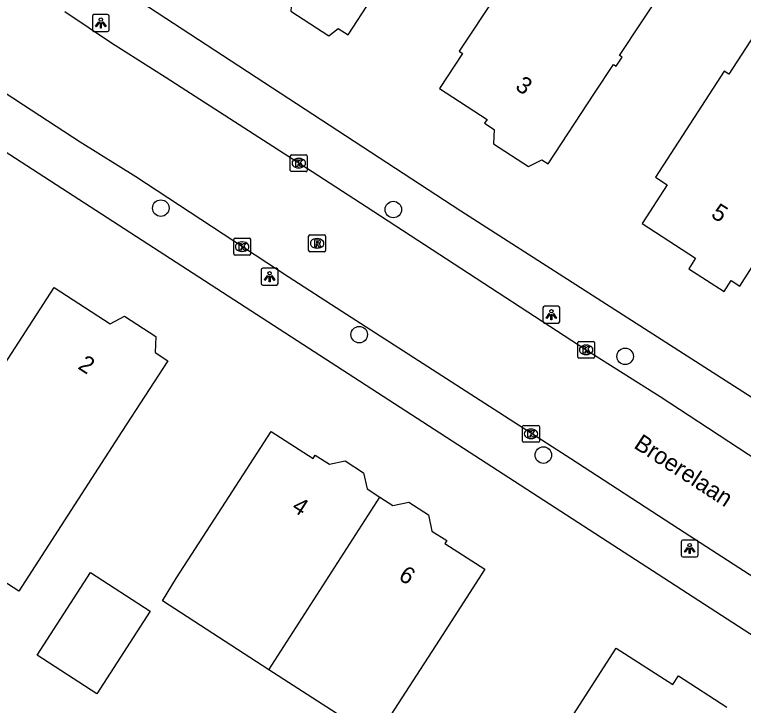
# Model space of a CAD drawing. Extents: x 161141 to 161601, y 381708 to 382245.
# Drawn here: x 161382.4 to 161425.51, y 382085.7 to 382126.58 of the extents above; entities that cross this region are included whole.
import ezdxf

# ---------------------------------------------------------------- set-up
doc = ezdxf.new("R2010")
doc.units = 0
for name, color, linetype in [('IMGEO_Boom', 7, 'Continuous'), ('IMGEO_Kolk', 7, 'Continuous'), ('IMGEO_Lichtpunt', 7, 'Continuous'), ('IMGEO_Openbare_ruimte_label', 7, 'Continuous'), ('IMGEO_Pand', 7, 'Continuous'), ('IMGEO_Pand_nummerreeks', 7, 'Continuous'), ('IMGEO_Rijbaan_lokaal_open', 7, 'Continuous'), ('IMGEO_Rioolput', 7, 'Continuous'), ('IMGEO_Voetpad_open', 7, 'Continuous')]:
    doc.layers.add(name, color=color, linetype=linetype)

msp = doc.modelspace()

# ---------------------------------------------------------------- linework, layer by layer
at = {"layer": 'IMGEO_Boom'}
for centre in [(161391.047, 382115.124), (161404.802, 382115.039), (161402.785, 382107.638), (161418.516, 382106.351), (161413.679, 382100.51)]:
    msp.add_circle(centre, 0.489, dxfattribs=at)
at = {"layer": 'IMGEO_Kolk'}
for p, q in [((161398.708, 382117.354), (161398.708, 382118.206)), ((161398.783, 382118.28), (161399.635, 382118.28)), ((161399.196, 382118.06), (161399.221, 382118.06)), ((161399.709, 382118.206), (161399.709, 382117.354)), ((161399.219, 382117.5), (161399.194, 382117.5)), ((161399.635, 382117.28), (161398.783, 382117.28)), ((161395.361, 382112.413), (161395.361, 382113.265)), ((161395.436, 382113.339), (161396.288, 382113.339)), ((161396.362, 382113.265), (161396.362, 382112.413)), ((161395.849, 382113.119), (161395.874, 382113.119)), ((161396.288, 382112.339), (161395.436, 382112.339)), ((161395.872, 382112.559), (161395.847, 382112.559)), ((161415.709, 382106.313), (161415.709, 382107.165)), ((161415.784, 382107.239), (161416.636, 382107.239)), ((161416.71, 382107.165), (161416.71, 382106.313)), ((161416.197, 382107.019), (161416.222, 382107.019)), ((161416.636, 382106.239), (161415.784, 382106.239)), ((161416.22, 382106.459), (161416.195, 382106.459)), ((161412.445, 382101.341), (161412.445, 382102.193)), ((161412.52, 382102.267), (161413.372, 382102.267)), ((161412.933, 382102.047), (161412.958, 382102.047)), ((161413.446, 382102.193), (161413.446, 382101.341)), ((161412.956, 382101.487), (161412.931, 382101.487)), ((161413.372, 382101.267), (161412.52, 382101.267))]:
    msp.add_line(p, q, dxfattribs=at)
for points in [[(161398.708, 382117.354), (161398.708, 382118.206)], [(161398.783, 382118.28), (161399.635, 382118.28)], [(161399.029, 382117.98), (161399.152, 382117.98), (161399.152, 382117.829), (161399.282, 382117.98), (161399.446, 382117.98), (161399.3, 382117.829), (161399.453, 382117.58), (161399.301, 382117.58), (161399.216, 382117.744), (161399.152, 382117.677), (161399.152, 382117.58), (161399.029, 382117.58), (161399.029, 382117.98)], [(161399.709, 382118.206), (161399.709, 382117.354)], [(161399.635, 382117.28), (161398.783, 382117.28)], [(161395.361, 382112.413), (161395.361, 382113.265)], [(161395.436, 382113.339), (161396.288, 382113.339)], [(161396.362, 382113.265), (161396.362, 382112.413)], [(161395.682, 382113.039), (161395.805, 382113.039), (161395.805, 382112.888), (161395.935, 382113.039), (161396.099, 382113.039), (161395.953, 382112.888), (161396.106, 382112.639), (161395.954, 382112.639), (161395.869, 382112.803), (161395.805, 382112.736), (161395.805, 382112.639), (161395.682, 382112.639), (161395.682, 382113.039)], [(161396.288, 382112.339), (161395.436, 382112.339)], [(161415.709, 382106.313), (161415.709, 382107.165)], [(161415.784, 382107.239), (161416.636, 382107.239)], [(161416.71, 382107.165), (161416.71, 382106.313)], [(161416.03, 382106.939), (161416.153, 382106.939), (161416.153, 382106.788), (161416.283, 382106.939), (161416.447, 382106.939), (161416.301, 382106.788), (161416.454, 382106.539), (161416.302, 382106.539), (161416.217, 382106.703), (161416.153, 382106.636), (161416.153, 382106.539), (161416.03, 382106.539), (161416.03, 382106.939)], [(161416.636, 382106.239), (161415.784, 382106.239)], [(161412.445, 382101.341), (161412.445, 382102.193)], [(161412.52, 382102.267), (161413.372, 382102.267)], [(161412.766, 382101.967), (161412.889, 382101.967), (161412.889, 382101.816), (161413.019, 382101.967), (161413.183, 382101.967), (161413.037, 382101.816), (161413.19, 382101.567), (161413.038, 382101.567), (161412.953, 382101.731), (161412.889, 382101.664), (161412.889, 382101.567), (161412.766, 382101.567), (161412.766, 382101.967)], [(161413.446, 382102.193), (161413.446, 382101.341)], [(161413.372, 382101.267), (161412.52, 382101.267)]]:
    msp.add_lwpolyline(points, dxfattribs=at)
for centre, start, end in [((161398.785, 382118.204), 91.552, 178.448), ((161398.785, 382118.204), 91.552, 178.448), ((161399.633, 382118.204), 1.552, 88.448), ((161399.633, 382118.204), 1.552, 88.448), ((161398.785, 382117.356), 181.552, 268.448), ((161398.785, 382117.356), 181.552, 268.448), ((161399.633, 382117.356), 271.552, 358.448), ((161399.633, 382117.356), 271.552, 358.448), ((161395.438, 382113.263), 91.552, 178.448), ((161395.438, 382113.263), 91.552, 178.448), ((161396.286, 382113.263), 1.552, 88.448), ((161396.286, 382113.263), 1.552, 88.448), ((161395.438, 382112.415), 181.552, 268.448), ((161395.438, 382112.415), 181.552, 268.448), ((161396.286, 382112.415), 271.552, 358.448), ((161396.286, 382112.415), 271.552, 358.448), ((161415.786, 382107.163), 91.552, 178.448), ((161415.786, 382107.163), 91.552, 178.448), ((161416.634, 382107.163), 1.552, 88.448), ((161416.634, 382107.163), 1.552, 88.448), ((161415.786, 382106.315), 181.552, 268.448), ((161415.786, 382106.315), 181.552, 268.448), ((161416.634, 382106.315), 271.552, 358.448), ((161416.634, 382106.315), 271.552, 358.448), ((161412.522, 382102.191), 91.552, 178.448), ((161412.522, 382102.191), 91.552, 178.448), ((161413.37, 382102.191), 1.552, 88.448), ((161413.37, 382102.191), 1.552, 88.448), ((161412.522, 382101.343), 181.552, 268.448), ((161412.522, 382101.343), 181.552, 268.448), ((161413.37, 382101.343), 271.552, 358.448), ((161413.37, 382101.343), 271.552, 358.448)]:
    msp.add_arc(centre, 0.0765, start, end, dxfattribs=at)
for centre, major_axis, ratio, start_param, end_param in [((161399.195, 382117.78), (-0.387, 0.002), 0.722429, 4.712389, 7.853982), ((161399.22, 382117.78), (-0.39, 0.002), 0.717154, 1.570796, 4.712389), ((161395.848, 382112.839), (-0.387, 0.002), 0.722429, 4.712389, 7.853982), ((161395.873, 382112.839), (-0.39, 0.002), 0.717154, 1.570796, 4.712389), ((161416.196, 382106.739), (-0.387, 0.002), 0.722429, 4.712389, 7.853982), ((161416.221, 382106.739), (-0.39, 0.002), 0.717154, 1.570796, 4.712389), ((161412.932, 382101.767), (-0.387, 0.002), 0.722429, 4.712389, 7.853982), ((161412.957, 382101.767), (-0.39, 0.002), 0.717154, 1.570796, 4.712389)]:
    msp.add_ellipse(centre, major_axis=major_axis, ratio=ratio, start_param=start_param, end_param=end_param, dxfattribs=at)
at = {"layer": 'IMGEO_Lichtpunt'}
for p, q in [((161387.901, 382126.575), (161387.093, 382126.575)), ((161387.901, 382126.575), (161387.093, 382126.575)), ((161386.999, 382126.48), (161386.999, 382125.673)), ((161386.999, 382126.48), (161386.999, 382125.673)), ((161387.995, 382125.673), (161387.995, 382126.48)), ((161387.995, 382125.673), (161387.995, 382126.48)), ((161387.093, 382125.579), (161387.901, 382125.579)), ((161387.093, 382125.579), (161387.901, 382125.579)), ((161396.985, 382111.471), (161396.985, 382110.664)), ((161396.985, 382111.471), (161396.985, 382110.664)), ((161397.887, 382111.566), (161397.079, 382111.566)), ((161397.887, 382111.566), (161397.079, 382111.566)), ((161397.981, 382110.664), (161397.981, 382111.471)), ((161397.981, 382110.664), (161397.981, 382111.471)), ((161397.079, 382110.57), (161397.887, 382110.57)), ((161397.079, 382110.57), (161397.887, 382110.57)), ((161414.554, 382109.315), (161413.746, 382109.315)), ((161414.554, 382109.315), (161413.746, 382109.315)), ((161413.652, 382109.22), (161413.652, 382108.413)), ((161413.652, 382109.22), (161413.652, 382108.413)), ((161414.648, 382108.413), (161414.648, 382109.22)), ((161414.648, 382108.413), (161414.648, 382109.22)), ((161413.746, 382108.319), (161414.554, 382108.319)), ((161413.746, 382108.319), (161414.554, 382108.319)), ((161422.737, 382095.48), (161421.929, 382095.48)), ((161422.737, 382095.48), (161421.929, 382095.48)), ((161421.835, 382095.385), (161421.835, 382094.578)), ((161421.835, 382095.385), (161421.835, 382094.578)), ((161422.831, 382094.578), (161422.831, 382095.385)), ((161422.831, 382094.578), (161422.831, 382095.385)), ((161421.929, 382094.484), (161422.737, 382094.484)), ((161421.929, 382094.484), (161422.737, 382094.484))]:
    msp.add_line(p, q, dxfattribs=at)
for points in [[(161387.373, 382126.144), (161387.412, 382126.116), (161387.224, 382125.854), (161387.186, 382125.881), (161387.373, 382126.144)], [(161387.475, 382126.096), (161387.522, 382126.096), (161387.522, 382125.774), (161387.475, 382125.774), (161387.475, 382126.096)], [(161387.585, 382126.116), (161387.623, 382126.143), (161387.81, 382125.881), (161387.771, 382125.853), (161387.585, 382126.116)], [(161397.359, 382111.135), (161397.398, 382111.107), (161397.21, 382110.845), (161397.172, 382110.872), (161397.359, 382111.135)], [(161397.461, 382111.087), (161397.508, 382111.087), (161397.508, 382110.765), (161397.461, 382110.765), (161397.461, 382111.087)], [(161397.571, 382111.107), (161397.609, 382111.134), (161397.796, 382110.872), (161397.757, 382110.844), (161397.571, 382111.107)], [(161414.026, 382108.884), (161414.065, 382108.856), (161413.877, 382108.594), (161413.839, 382108.621), (161414.026, 382108.884)], [(161414.128, 382108.836), (161414.175, 382108.836), (161414.175, 382108.514), (161414.128, 382108.514), (161414.128, 382108.836)], [(161414.238, 382108.856), (161414.276, 382108.883), (161414.463, 382108.621), (161414.424, 382108.593), (161414.238, 382108.856)], [(161422.209, 382095.049), (161422.248, 382095.021), (161422.06, 382094.759), (161422.022, 382094.786), (161422.209, 382095.049)], [(161422.421, 382095.021), (161422.459, 382095.048), (161422.646, 382094.786), (161422.607, 382094.758), (161422.421, 382095.021)], [(161422.311, 382095.001), (161422.358, 382095.001), (161422.358, 382094.679), (161422.311, 382094.679), (161422.311, 382095.001)]]:
    msp.add_lwpolyline(points, dxfattribs=at)
for centre in [(161387.498, 382126.278), (161397.484, 382111.269), (161414.151, 382109.018), (161422.334, 382095.183)]:
    msp.add_circle(centre, 0.0994, dxfattribs=at)
for centre, start, end in [((161387.093, 382126.48), 90, 180), ((161387.093, 382126.48), 90, 180), ((161387.901, 382126.48), 0, 90), ((161387.901, 382126.48), 0, 90), ((161387.093, 382125.673), 180, 270), ((161387.093, 382125.673), 180, 270), ((161387.901, 382125.673), 270, 0), ((161387.901, 382125.673), 270, 360), ((161397.079, 382111.471), 90, 180), ((161397.079, 382111.471), 90, 180), ((161397.887, 382111.471), 0, 90), ((161397.887, 382111.471), 0, 90), ((161397.079, 382110.664), 180, 270), ((161397.079, 382110.664), 180, 270), ((161397.887, 382110.664), 270, 0), ((161397.887, 382110.664), 270, 360), ((161413.746, 382109.22), 90, 180), ((161413.746, 382109.22), 90, 180), ((161414.554, 382109.22), 0, 90), ((161414.554, 382109.22), 0, 90), ((161413.746, 382108.413), 180, 270), ((161413.746, 382108.413), 180, 270), ((161414.554, 382108.413), 270, 0), ((161414.554, 382108.413), 270, 360), ((161421.929, 382095.385), 90, 180), ((161421.929, 382095.385), 90, 180), ((161422.737, 382095.385), 0, 90), ((161422.737, 382095.385), 0, 90), ((161421.929, 382094.578), 180, 270), ((161421.929, 382094.578), 180, 270), ((161422.737, 382094.578), 270, 0), ((161422.737, 382094.578), 270, 360)]:
    msp.add_arc(centre, 0.0946, start, end, dxfattribs=at)
at = {"layer": 'IMGEO_Pand'}
for points in [[(161411.481, 382134.059), (161408.295, 382136.12), (161407.65, 382135.123), (161401.554, 382139.067), (161400.661, 382137.729), (161398.193, 382133.914), (161395.476, 382129.716), (161398.267, 382127.909), (161398.155, 382127.736), (161398.771, 382127.338), (161398.742, 382126.773), (161400.996, 382125.315), (161401.533, 382125.759), (161402.135, 382125.37), (161404.852, 382129.568), (161405.639, 382130.788), (161408.274, 382129.089), (161411.371, 382133.888)], [(161410.877, 382127.733), (161408.688, 382124.408), (161408.897, 382124.27), (161407.531, 382122.195), (161410.35, 382120.372), (161410.202, 382120.144), (161410.763, 382119.782), (161410.72, 382118.935), (161412.799, 382117.589), (161413.578, 382117.987), (161413.963, 382117.738), (161416.713, 382121.915), (161417.832, 382123.614), (161417.982, 382123.514), (161418.34, 382124.06), (161418.188, 382124.158), (161420.742, 382128.036)], [(161426.411, 382125.757), (161424.649, 382123.042), (161424.369, 382123.223), (161423.028, 382121.15), (161420.311, 382116.952), (161421.01, 382116.5), (161419.524, 382114.203), (161422.684, 382112.158), (161422.284, 382111.54), (161424.378, 382110.185), (161424.796, 382110.831), (161425.295, 382110.508), (161426.632, 382112.574)], [(161375.556, 382101.873), (161375.671, 382102.05), (161378.237, 382100.391), (161384.729, 382110.433), (161388.052, 382108.285), (161388.906, 382108.722), (161390.752, 382107.529), (161390.705, 382106.586), (161391.463, 382106.096), (161388.749, 382101.898), (161385.152, 382096.335), (161382.643, 382092.455), (161376.11, 382096.68), (161372.874, 382091.675), (161370.095, 382093.472), (161372.141, 382096.619)], [(161397.438, 382087.809), (161391.146, 382091.877), (161391.97, 382093.238), (161394.864, 382097.714), (161397.578, 382101.913), (161400.051, 382100.314), (161400.18, 382100.512), (161401.027, 382099.965), (161401.953, 382100.163), (161403.047, 382099.456), (161403.251, 382098.506), (161404.008, 382098.017)], [(161404.008, 382098.017), (161404.764, 382097.529), (161405.713, 382097.732), (161406.876, 382096.98), (161407.084, 382096.013), (161407.959, 382095.447), (161407.856, 382095.287), (161410.219, 382093.759), (161407.505, 382089.561), (161403.739, 382083.736), (161397.438, 382087.809)], [(161397.438, 382087.809), (161404.008, 382098.017)], [(161387.254, 382086.383), (161383.725, 382088.664), (161386.887, 382093.556), (161390.416, 382091.275), (161387.254, 382086.383)], [(161418.44, 382076.177), (161415.195, 382078.275), (161414.276, 382076.854), (161413.146, 382077.584), (161411.323, 382078.762), (161415.281, 382084.884), (161417.995, 382089.083), (161421.331, 382086.926), (161421.664, 382087.44), (161424.527, 382085.589)]]:
    msp.add_lwpolyline(points, dxfattribs=at)
at = {"layer": 'IMGEO_Rijbaan_lokaal_open'}
for points in [[(161499.796, 382045.589), (161498.051, 382046.741), (161477.592, 382059.945), (161473.195, 382062.836), (161460.477, 382071.037), (161453.542, 382075.54), (161442.527, 382082.644), (161435.549, 382087.163), (161421.669, 382096.147), (161415.306, 382100.289), (161401.761, 382109.008), (161398.574, 382111.058), (161389.569, 382116.981), (161386.277, 382119.018), (161382.915, 382121.211), (161379.746, 382123.279), (161360.833, 382135.554)], [(161385.362, 382126.757), (161388.136, 382124.895), (161391.361, 382122.845), (161399.992, 382117.288), (161403.197, 382115.21), (161416.21, 382106.739), (161420.597, 382103.968), (161426.931, 382099.82), (161440.905, 382090.804), (161444.055, 382088.754), (161453.24, 382082.778), (161460.192, 382078.284), (161467.324, 382073.702), (161468.287, 382073.003), (161471.488, 382070.983), (161480.028, 382065.466), (161483.251, 382063.426), (161485.554, 382061.86), (161494.669, 382055.998), (161498.469, 382053.534), (161512.078, 382044.654), (161521.765, 382038.348), (161525.596, 382035.854)]]:
    msp.add_lwpolyline(points, dxfattribs=at)
at = {"layer": 'IMGEO_Rioolput'}
for p, q in [((161399.793, 382112.612), (161399.793, 382113.464)), ((161399.868, 382113.538), (161400.72, 382113.538)), ((161400.281, 382113.318), (161400.306, 382113.318)), ((161400.794, 382113.464), (161400.794, 382112.612)), ((161400.304, 382112.758), (161400.279, 382112.758)), ((161400.72, 382112.538), (161399.868, 382112.538))]:
    msp.add_line(p, q, dxfattribs=at)
for points in [[(161399.793, 382112.612), (161399.793, 382113.464)], [(161399.868, 382113.538), (161400.72, 382113.538)], [(161400.382, 382113.236), (161400.13, 382113.238), (161400.13, 382112.838)], [(161400.308, 382113.157), (161400.254, 382113.157), (161400.254, 382113.076)], [(161400.794, 382113.464), (161400.794, 382112.612)], [(161400.13, 382112.838), (161400.254, 382112.838), (161400.254, 382113), (161400.265, 382113)], [(161400.254, 382113.076), (161400.306, 382113.076)], [(161400.312, 382112.971), (161400.383, 382112.838), (161400.523, 382112.838), (161400.458, 382112.964)], [(161400.72, 382112.538), (161399.868, 382112.538)]]:
    msp.add_lwpolyline(points, dxfattribs=at)
for centre, radius, start, end in [((161399.87, 382113.462), 0.0765, 91.552, 178.448), ((161399.87, 382113.462), 0.0765, 91.552, 178.448), ((161400.314, 382113.061), 0.0964, 77.0061, 93.1865), ((161400.328, 382113.118), 0.0378, 276.6634, 79.6772), ((161400.381, 382113.126), 0.109, 350.3612, 89.416), ((161400.718, 382113.462), 0.0765, 1.552, 88.448), ((161400.718, 382113.462), 0.0765, 1.552, 88.448), ((161400.264, 382112.947), 0.0533, 26.0293, 88.6989), ((161400.29, 382113.265), 0.19, 274.7715, 282.9687), ((161400.379, 382113.126), 0.112, 277.5842, 350.9817), ((161400.363, 382112.911), 0.108, 29.5134, 73.7905), ((161399.87, 382112.614), 0.0765, 181.552, 268.448), ((161399.87, 382112.614), 0.0765, 181.552, 268.448), ((161400.718, 382112.614), 0.0765, 271.552, 358.448), ((161400.718, 382112.614), 0.0765, 271.552, 358.448)]:
    msp.add_arc(centre, radius, start, end, dxfattribs=at)
for centre, major_axis, ratio, start_param, end_param in [((161400.28, 382113.038), (-0.387, 0.002), 0.722429, 4.712389, 7.853982), ((161400.305, 382113.038), (-0.39, 0.002), 0.717154, 1.570796, 4.712389)]:
    msp.add_ellipse(centre, major_axis=major_axis, ratio=ratio, start_param=start_param, end_param=end_param, dxfattribs=at)
at = {"layer": 'IMGEO_Voetpad_open'}
for points in [[(161523.437, 382040.853), (161500, 382056.07), (161450.498, 382088.211), (161408.789, 382114.947), (161389.855, 382127.317), (161365.175, 382143.293), (161365.084, 382143.565)], [(161359.011, 382133.266), (161498.24, 382043.117)]]:
    msp.add_lwpolyline(points, dxfattribs=at)

# ---------------------------------------------------------------- texts
at = {"layer": 'IMGEO_Openbare_ruimte_label'}
msp.add_text('Broerelaan', height=1, rotation=326.9137, dxfattribs=at).set_placement((161418.973, 382100.972))
at = {"layer": 'IMGEO_Pand_nummerreeks'}
for s, rotation, p in [('3', 325.2803, (161411.956, 382122.194)), ('5', 327.3698, (161423.536, 382114.626)), ('2', 327.2154, (161386.087, 382105.656)), ('4', 327.1762, (161398.728, 382097.268)), ('6', 327.1762, (161405.049, 382093.191))]:
    msp.add_text(s, height=1, rotation=rotation, dxfattribs=at).set_placement(p)

doc.saveas('drawing.dxf')
